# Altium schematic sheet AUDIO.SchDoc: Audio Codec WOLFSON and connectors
size A4; Date: 25-FEB-2015; Author: A.B; CompanyName: STMicroelectronics; Address1: 12, Rue Jules HOROWITZ; Address2: 38019 Grenoble; Address3: FRANCE; DocumentNumber: MB1191; Revision: B-02; SheetNumber: 6; SheetTotal: 14; Project: STM32F746G-DISCO
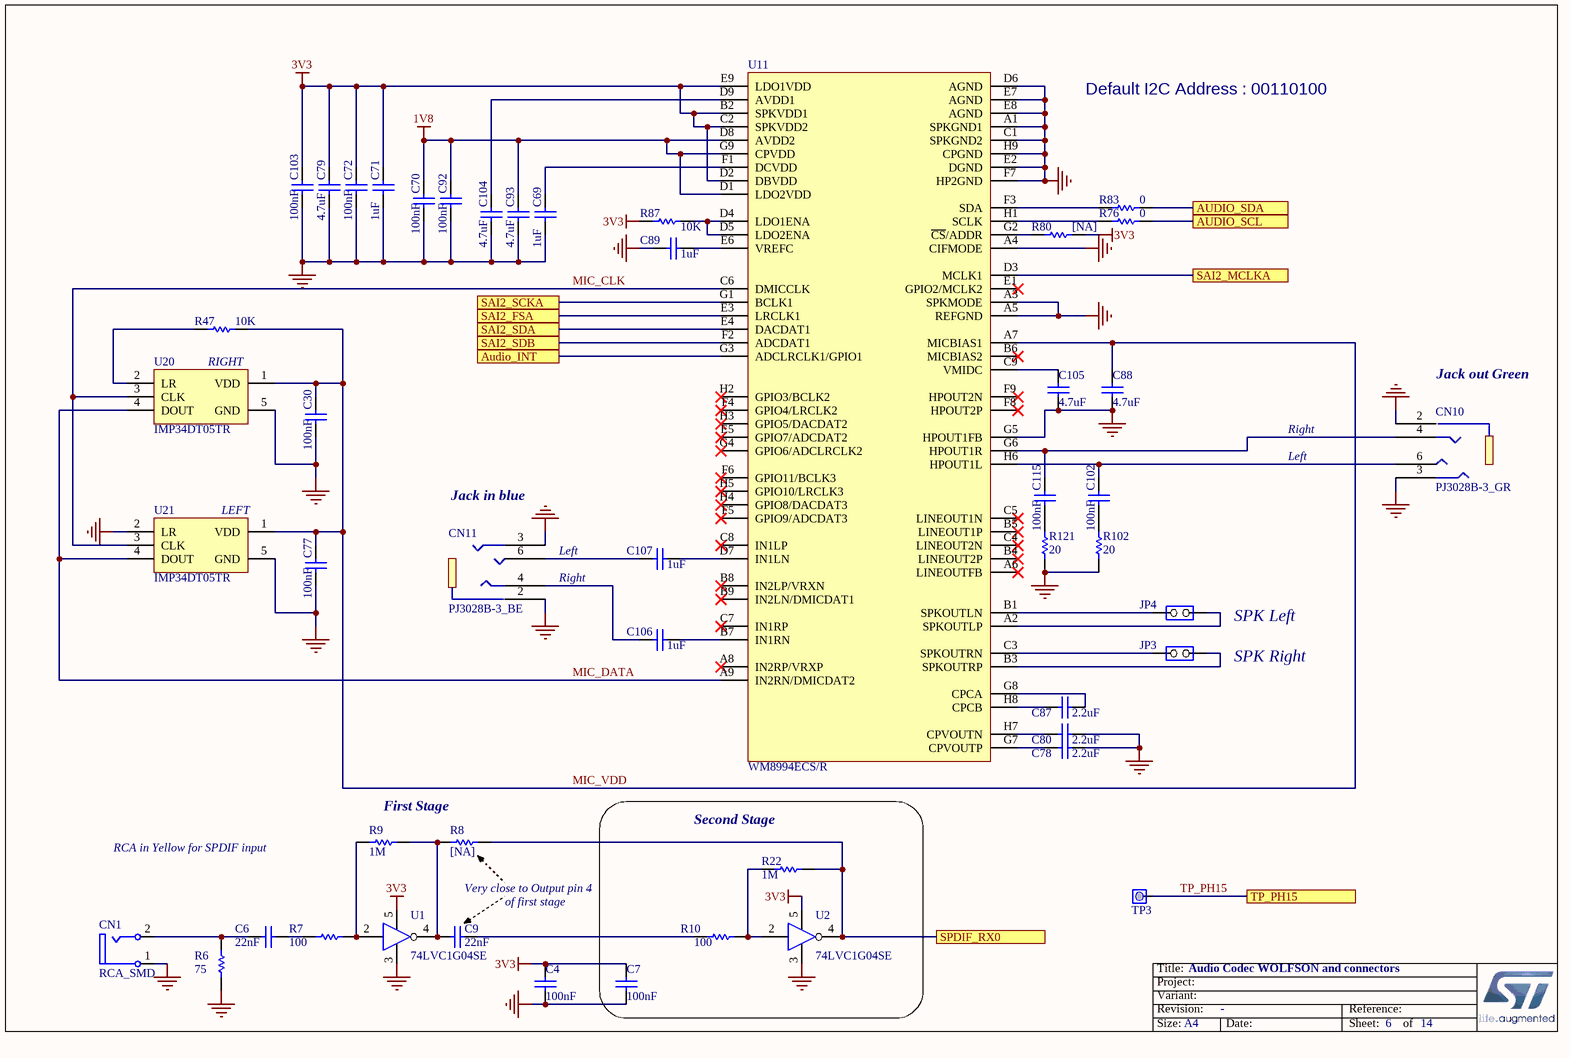
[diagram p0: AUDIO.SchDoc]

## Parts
C4  100nF  [0402C]
C6  22nF  [0402C]
C7  100nF  [0402C]
C9  22nF  [0402C]
C30  100nF  [0402C]
C69  1uF  [0603C]
C70  100nF  [0402C]
C71  1uF  [0603C]
C72  100nF  [0402C]
C77  100nF  [0402C]
C78  2.2uF  [0603C]
C79  4.7uF  [0603C]
C80  2.2uF  [0603C]
C87  2.2uF  [0603C]
C88  4.7uF  [0603C]
C89  1uF  [0603C]
C92  100nF  [0402C]
C93  4.7uF  [0603C]
C102  100nF  [0402C]
C103  100nF  [0402C]
C104  4.7uF  [0603C]
C105  4.7uF  [0603C]
C106  1uF  [0603C]
C107  1uF  [0603C]
C115  100nF  [0402C]
CN1  RCA_SMD  [RCA_SMD]
CN10  PJ3028B-3_GR  [PJ3028B]
CN11  PJ3028B-3_BE  [PJ3028B]
JP3  Jumper 2 pins  [SIP2/2.54]  (value not drawn)
JP4  Jumper 2 pins  [SIP2/2.54]  (value not drawn)
R6  75  [0402R]
R7  100  [0402R]
R8  [NA]  [0402R]
R9  1M  [0402R]
R10  100  [0402R]
R22  1M  [0402R]
R47  10K  [0402R]
R76  0  [0402R]
R80  [NA]  [0402R]
R83  0  [0402R]
R87  10K  [0402R]
R102  20  [0402R]
R121  20  [0402R]
TP3  Test point 1 pin with hole  [SIP1/2.54]  (value not drawn)
U1  74LVC1G04SE  [SOT353]
U2  74LVC1G04SE  [SOT353]
U11  WM8994ECS/R  [BGA72_0R5_4R5X4]
U20  IMP34DT05TR  [HCLGA_3X4X1_4LD]
U21  IMP34DT05TR  [HCLGA_3X4X1_4LD]

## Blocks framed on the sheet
Second Stage: C7 R10 R22 U2

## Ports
Audio_INT, AUDIO_SCL, AUDIO_SDA, SAI2_FSA, SAI2_MCLKA, SAI2_SCKA, SAI2_SDA, SAI2_SDB, SPDIF_RX0, TP_PH15

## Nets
1V8: C70.1 C92.1 C93.1 U11.D1(LDO2VDD) U11.D8(AVDD2) U11.G9(CPVDD)
3V3: C4.2 C7.2 C71.2 C72.1 C79.1 C103.1 R80.2 R87.2 U1.5(VCC) U2.5(VCC) U11.B2(SPKVDD1) U11.C2(SPKVDD2) U11.D2(DBVDD) U11.E9(LDO1VDD)
GND: C4.1 C7.1 C30.2 C69.1 C70.2 C71.1 C72.2 C77.2 C78.2 C79.2 C80.2 C88.1 C89.2 C92.2 C93.2 C103.2 C104.2 C105.1 CN1.1(Ground) CN10.2 CN10.3 CN11.2 CN11.3 R6.1 R102.2 R121.2 U1.3(GND) U2.3(GND) U11.A1(SPKGND1) U11.A3(SPKMODE) U11.A4(CIFMODE) U11.A5(REFGND) U11.C1(SPKGND2) U11.D6(AGND) U11.E2(DGND) U11.E7(AGND) U11.E8(AGND) U11.F7(HP2GND) U11.G5(HPOUT1FB) U11.H9(CPGND) U20.5(GND) U21.2(LR) U21.5(GND)
Audio_INT: U11.G3(ADCLRCLK1/GPIO1) ; port Audio_INT
AUDIO_SCL: R76.1 ; port AUDIO_SCL
AUDIO_SDA: R83.1 ; port AUDIO_SDA
MIC_CLK: U11.C6(DMICCLK) U20.3(CLK) U21.3(CLK)
MIC_DATA: U11.A9(IN2RN/DMICDAT2) U20.4(DOUT) U21.4(DOUT)
MIC_VDD: C30.1 C77.1 C88.2 R47.2 U11.A7(MICBIAS1) U20.1(VDD) U21.1(VDD)
SAI2_FSA: U11.E3(LRCLK1) ; port SAI2_FSA
SAI2_MCLKA: U11.D3(MCLK1) ; port SAI2_MCLKA
SAI2_SCKA: U11.G1(BCLK1) ; port SAI2_SCKA
SAI2_SDA: U11.E4(DACDAT1) ; port SAI2_SDA
SAI2_SDB: U11.F2(ADCDAT1) ; port SAI2_SDB
SPDIF_RX0: R8.2 R22.2 U2.4(Y) ; port SPDIF_RX0
TP_PH15: TP3.1(COMMON) ; port TP_PH15
NetC6_1: C6.1 CN1.2(Signal) R6.2
NetC6_2: C6.2 R7.1
NetC9_1: C9.1 R8.1 R9.2 U1.4(Y)
NetC9_2: C9.2 R10.1
NetC69_2: C69.2 U11.F1(DCVDD)
NetC78_1: C78.1 U11.G7(CPVOUTP)
NetC80_1: C80.1 U11.H7(CPVOUTN)
NetC87_1: C87.1 U11.H8(CPCB)
NetC87_2: C87.2 U11.G8(CPCA)
NetC89_1: C89.1 U11.E6(VREFC)
NetC102_1: C102.1 CN10.6 U11.H6(HPOUT1L)
NetC102_2: C102.2 R102.1
NetC104_1: C104.1 U11.D9(AVDD1)
NetC105_2: C105.2 U11.C9(VMIDC)
NetC106_1: C106.1 U11.B7(IN1RN)
NetC106_2: C106.2 CN11.4
NetC107_1: C107.1 U11.D7(IN1LN)
NetC107_2: C107.2 CN11.6
NetC115_1: C115.1 CN10.4 U11.G6(HPOUT1R)
NetC115_2: C115.2 R121.1
NetJP3_1: JP3.1(COMMON) U11.C3(SPKOUTRN)
NetJP3_2: JP3.2(NO) U11.B3(SPKOUTRP)
NetJP4_1: JP4.1(COMMON) U11.B1(SPKOUTLN)
NetJP4_2: JP4.2(NO) U11.A2(SPKOUTLP)
NetR7_2: R7.2 R9.1 U1.2(A)
NetR10_2: R10.2 R22.1 U2.2(A)
NetR47_1: R47.1 U20.2(LR)
NetR76_2: R76.2 U11.H1(SCLK)
NetR80_1: R80.1 U11.G2(~{CS}/ADDR)
NetR83_2: R83.2 U11.F3(SDA)
NetR87_1: R87.1 U11.D4(LDO1ENA) U11.D5(LDO2ENA)

Not connected (* = marked no-connect by the designer): U1 1(NC); U2 1(NC); U11 A6(LINEOUTFB)* A8(IN2RP/VRXP)* B4(LINEOUT2P)* B5(LINEOUT1P)* B6(MICBIAS2)* B8(IN2LP/VRXN)* B9(IN2LN/DMICDAT1)* C4(LINEOUT2N)* C5(LINEOUT1N)* C7(IN1RP)* C8(IN1LP)* E1(GPIO2/MCLK2)* E5(GPIO7/ADCDAT2)* F4(GPIO4/LRCLK2)* F5(GPIO9/ADCDAT3)* F6(GPIO11/BCLK3)* F8(HPOUT2P)* F9(HPOUT2N)* G4(GPIO6/ADCLRCLK2)* H2(GPIO3/BCLK2)* H3(GPIO5/DACDAT2)* H4(GPIO8/DACDAT3)* H5(GPIO10/LRCLK3)*

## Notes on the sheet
- Default I2C Address : 00110100
- (near U20) RIGHT
- (near CN10) Jack out Green
- Right
- (near U21) LEFT
- (near CN11) Jack in blue
- Left
- SPK Left
- SPK Right
- RCA in Yellow for SPDIF input
- First Stage
- Very close to Output pin 4
- of first stage

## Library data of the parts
C4 C7 C30 C70 C72 C77 C92 C102 C103 C115 = Cap_100nF_X7R_10%_0402: Capacitor,100nF,16V,X7R,10%,0402,YAGEO; Manuf_Part_1: CC0402KRX7R7BB104
C6 C9 = Cap_22nF_X7R_10%_0402: Capacitor,22nF,16V,X7R,10%,0402,YAGEO; Manuf_Part_1: CC0402KRX7R7BB223
C69 C71 C89 C106 C107 = Cap_1uF_X5R_10%_0603: Capacitor,1uF,16V,X5R,10%,0603,YAGEO; Manuf_Part_1: CC0603KRX5R7BB105
C78 C80 C87 = Cap_2.2uF_X5R_10%_0603: Capacitor,2.2uF,10V, X5R,10%,0603,YAGEO; Manuf_Part_1: CC0603KRX5R6BB225; Manuf_Part_2: C0603C225K8PACTU; Manuf_2: KEMET
C79 C88 C93 C104 C105 = Cap_4.7uF_X5R_10%_0603: Capacitor,4.7uF,16V, X5R,10%,0603,YAGEO; Manuf_Part_1: CC0603KRX5R7BB475; Order: CC0603KRX5R7BB105
CN1 = RCA_SMD: RCA Phono Jack, Right Angle, SMD, Yellow; Manuf_Part_1: JBB0819100002; Manuf_1: Jiubaba
CN10 = PJ3028B-3_GR: Connector Jack Stereo 3.5mm, female SMT, Green (Line output); Manuf_1: qiaod; Manuf_Part_2: PJ30280-3_GR
CN11 = PJ3028B-3_BE: Connector Jack Stereo 3.5mm, female SMT, Blue (Line input); Manuf_1: qiaod; Manuf_Part_2: PJ30280-3_BE
JP3 JP4 = Jumper2: Fitted: NO
R6 = Res_75_1%_0402: Resistor,75,0402,1%,YAGEO; Manuf_Part_1: RC0402FR-0775RL; Order: 311-75.0LRTR-ND
R7 R10 = Res_100_1%_0402: Resistor,100,0402,1%,YAGEO; Manuf_Part_1: RC0402FR-07100RL; Order: 9239111
R8 R80 = Res_NA_0402: Resistor,[NA],0402; Fitted: NO
R9 R22 = Res_1M_1%_0402: Resistor,1M,0402,1%,YAGEO; Manuf_Part_1: RC0402FR-071ML
R47 R87 = Res_10K_1%_0402: Resistor,10K,0402,1%,YAGEO; Manuf_Part_1: RC0402FR-0710KL
R76 R83 = Res_0_5%_0402: Resistor,0,0402,5%,YAGEO; Manuf_Part_1: RC0402JR-070RL; Order: 2363467
R102 R121 = Res_20_1%_0402: Resistor,20,0402,1%,YAGEO; Manuf_Part_1: RC0402FR-0720RL
TP3 = TP1: Test Point; Fitted: NO
U1 U2 = 74LVC1G04SE: Single inverter gate with a standard push-pull output. (1.65V to 5.5V); Manuf_Part_1: 74LVC1G04SE-7; Manuf_1: DIODES; Order: 1845218; ECCN_US/EU: EAR99/NEC
U11 = WM8994ECS/R: Multi-Channel Audio Hub CODEC for Smartphones; Manuf_1: Cirrus Logic; ECCN_US/EU: EAR99/NEC
U20 U21 = IMP34DT05TR: MEMS audio sensor omnidirectional digital microphone for industrial applications; Manuf_1: STMICROELECTRONICS; ECCN_US/EU: EAR99/NEC; provided: SUBCO with ST control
